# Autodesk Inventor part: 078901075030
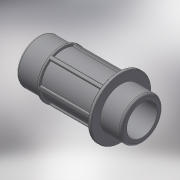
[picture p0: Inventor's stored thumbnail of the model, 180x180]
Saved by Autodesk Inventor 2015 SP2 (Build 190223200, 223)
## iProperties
Created: 2018-02
Part Number: 078901075030
Material: Generic
Description: PLASSON THREADED MALE ADAPTOR 75-3"
Document SubType Name: Modeling
Designer: KIM
Density: 1 g/cm^3
Appearance: Default
Author: KIM
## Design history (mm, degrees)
derived "078901.ipt"
feature "Solid1::078901.ipt"
tag "TaggingFeature1"
body "Solid1"
other parameters: "d4" = 4.3942, "d14" = 7.03072, "d15" = 3.51536, "d17" = 0, "d20" = 360 deg, "d40" = 33, "d41" = 87.884, "d45" = 96.6724, "d46" = 61.5188, "d47" = 3.3, "d77" = 137, "d78" = 75, "d85" = 0.87884, "d91" = 27.4, "d103" = 31.51, "d105" = 0.87884, "R_" = 87.884, "l_2" = 33, "l_" = 137, "d_" = 75
